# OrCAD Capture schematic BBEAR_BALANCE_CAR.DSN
size A4; title: RTU_BBear; rev: v1.0
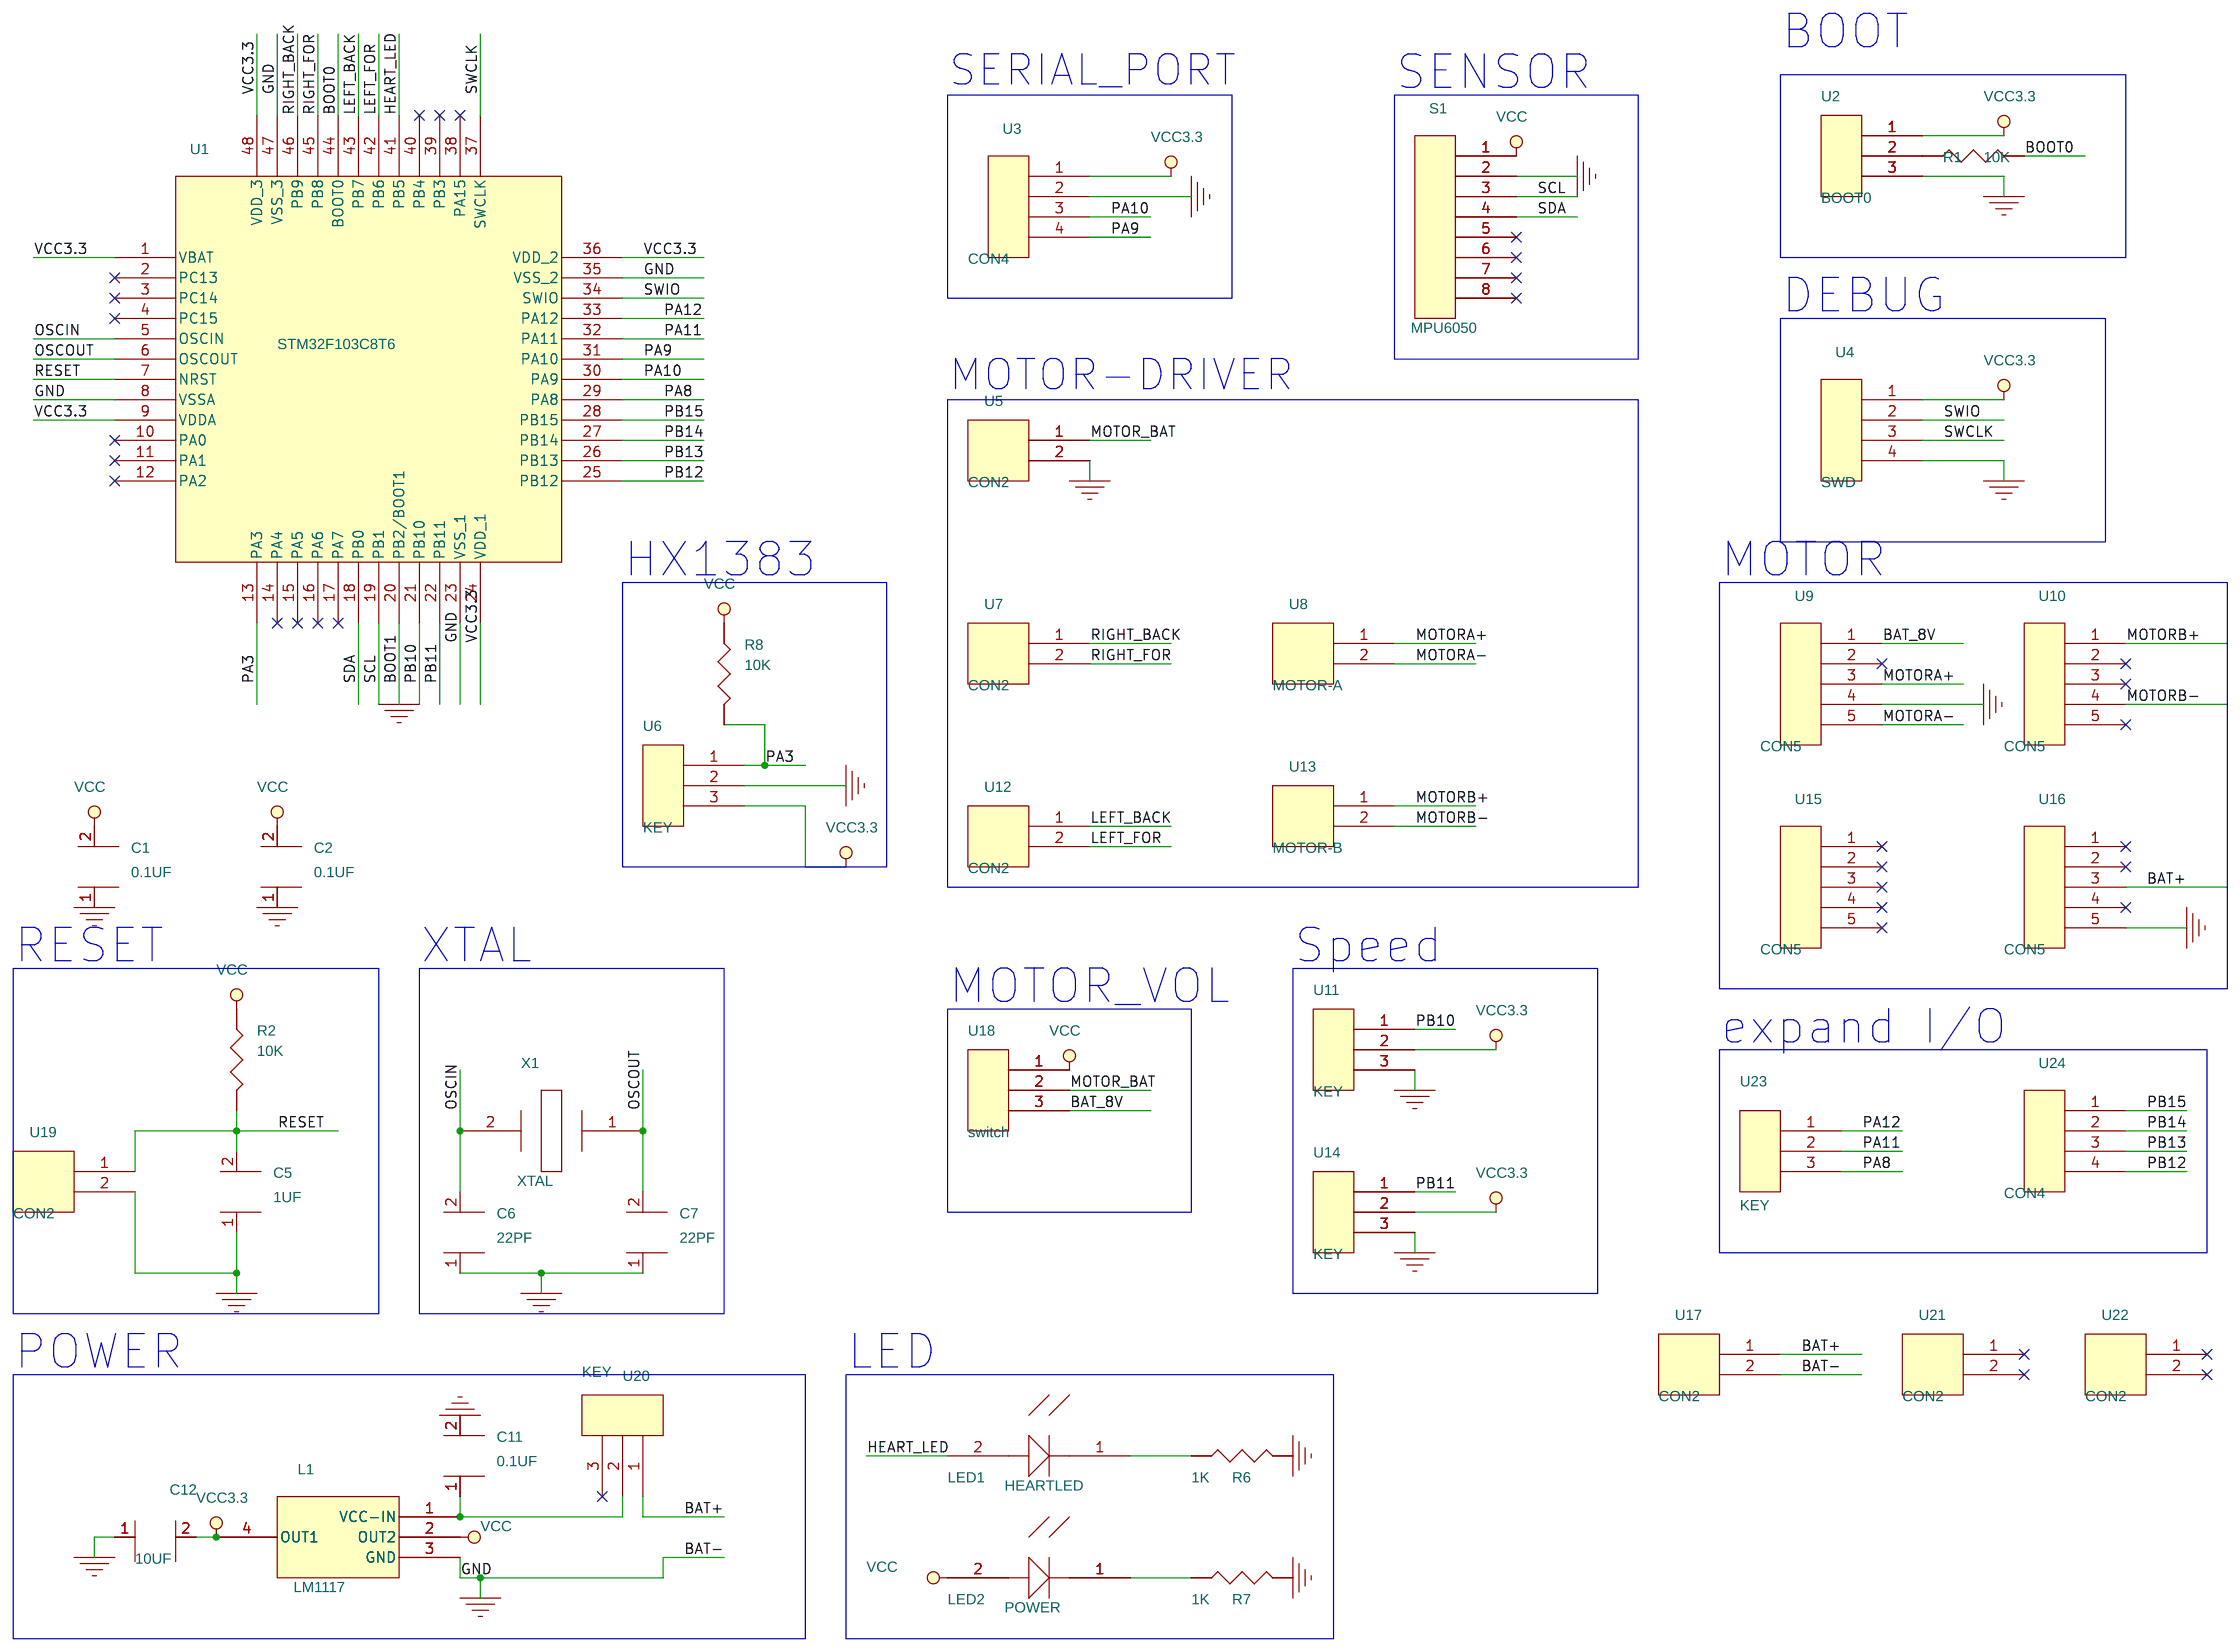
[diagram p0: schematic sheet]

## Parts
C1  0.1UF  [c-0805]
C2  0.1UF  [c-0805]
C5  1UF  [c-0805]
C6  22PF  [c-0805]
C7  22PF  [c-0805]
C11  0.1UF  [c-0805]
C12  10UF  [c-0805]
L1  LM1117  [LM1117_3_3]
LED1  HEARTLED  [c-0805]
LED2  POWER  [c-0805]
R1  10K  [c-0805]
R2  10K  [c-0805]
R6  1K  [c-0805]
R7  1K  [c-0805]
R8  10K  [c-0805]
S1  MPU6050  [CON8]
U1  STM32F103C8T6  [ncu100_lqfp_48]
U2  BOOT0  [CON3]
U3  CON4  [CON4]
U4  SWD  [CON4]
U5  CON2  [CON2_R2_54]
U6  KEY  [CON3]
U7  CON2  [CON2_R2_54]
U8  MOTOR-A  [CON2_R2_54]
U9  CON5  [tp2_54_5]
U10  CON5  [tp2_54_5]
U11  KEY  [CON3]
U12  CON2  [CON2_R2_54]
U13  MOTOR-B  [CON2_R2_54]
U14  KEY  [CON3]
U15  CON5  [tp2_54_5]
U16  CON5  [tp2_54_5]
U17  CON2  [CON2_R2_54]
U18  switch  [CON3]
U19  CON2  [3_6key]
U20  KEY  [CON3]
U21  CON2  [P4_003_20]
U22  CON2  [P4_003_20]
U23  KEY  [CON3]
U24  CON4  [CON4]
X1  XTAL  [xtal]

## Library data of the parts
C1 C2 C5-C7 C11 C12 = CAP
L1 = LM1117
LED1 LED2 = LED
R1 R2 R6-R8 = R
S1 = CON8
U1 = STM32F103C8T6
U2 U6 U11 U14 U18 U20 U23 = CON3
U3 U4 U24 = CON4
U5 U7 U8 U12 U13 U17 U19 U21 U22 = CON2
U9 U10 U15 U16 = CON5
X1 = XTAL

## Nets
GND: C1.1 C2.1 C5.1 C6.1 C7.1 C11.2 C12.1 L1.3(GND) R6.2 R7.2 S1.2 U1.8(VSSA) U1.20(PB2/BOOT1) U1.23(VSS_1) U1.35(VSS_2) U1.47(VSS_3) U2.3 U3.2 U4.4 U5.2 U6.2 U9.4 U11.3 U14.3 U16.5 U17.2 U19.2
VCC3.3: C1.2 C2.2 C12.2 L1.2(OUT2) L1.4(OUT1) LED2.2 R2.1 R8.1 S1.1 U1.1(VBAT) U1.9(VDDA) U1.24(VDD_1) U1.36(VDD_2) U1.48(VDD_3) U2.1 U3.1 U4.1 U6.3 U11.2 U14.2 U18.1
BAT+: U16.3 U17.1 U20.1
BAT_8V: U9.1 U18.3
BOOT0: R1.2 U1.44(BOOT0)
HEART_LED: LED1.2 U1.41(PB5)
LEFT_BACK: U1.43(PB7) U12.1
LEFT_FOR: U1.42(PB6) U12.2
MOTOR_BAT: U5.1 U18.2
MOTORA+: U8.1 U9.3
MOTORA-: U8.2 U9.5
MOTORB+: U10.1 U13.1
MOTORB-: U10.4 U13.2
OSCIN: C6.2 U1.5(OSCIN) X1.2
OSCOUT: C7.2 U1.6(OSCOUT) X1.1
PA3: R8.2 U1.13(PA3) U6.1
PA8: U1.29(PA8) U23.3
PA9: U1.31(PA10) U3.4
PA10: U1.30(PA9) U3.3
PA11: U1.32(PA11) U23.2
PA12: U1.33(PA12) U23.1
PB10: U1.21(PB10) U11.1
PB11: U1.22(PB11) U14.1
PB12: U1.25(PB12) U24.4
PB13: U1.26(PB13) U24.3
PB14: U1.27(PB14) U24.2
PB15: U1.28(PB15) U24.1
RESET: C5.2 R2.2 U1.7(NRST) U19.1
RIGHT_BACK: U1.46(PB9) U7.1
RIGHT_FOR: U1.45(PB8) U7.2
SCL: S1.3 U1.19(PB1)
SDA: S1.4 U1.18(PB0)
SWCLK: U1.37(SWCLK) U4.3
SWIO: U1.34(SWIO) U4.2
N00802: C11.1 L1.1(VCC-IN) U20.2
N03806: LED2.1 R7.1
N07785: LED1.1 R6.1
N42275: R1.1 U2.2

Not connected (* = marked no-connect by the designer): S1 5* 6* 7* 8*; U1 2(PC13)* 3(PC14)* 4(PC15)* 10(PA0)* 11(PA1)* 12(PA2)* 14(PA4)* 15(PA5)* 16(PA6)* 17(PA7)* 38(PA15)* 39(PB3)* 40(PB4)*; U9 2*; U10 2* 3* 5*; U15 1* 2* 3* 4* 5*; U16 1* 2* 4*; U20 3*; U21 1* 2*; U22 1* 2*

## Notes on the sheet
- BOOT
- SERIAL_PORT
- SENSOR
- DEBUG
- MOTOR-DRIVER
- HX1383
- MOTOR
- RESET
- XTAL
- Speed
- MOTOR_VOL
- expand I/O
- POWER
- LED
